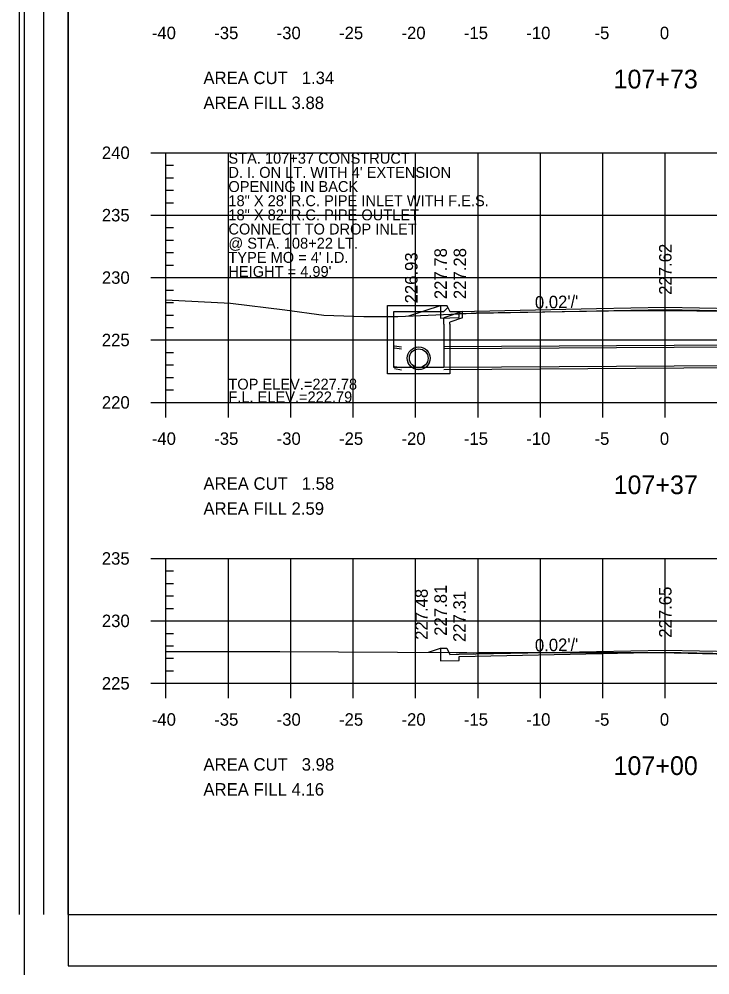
# Model space of a CAD drawing. Extents: x 1367903 to 1373764, y 376865 to 382130.
# Drawn here: x 1371640.9 to 1371751.5, y 377279.1 to 377432.3 of the extents above; entities that cross this region are included whole.
import ezdxf

# ---------------------------------------------------------------- set-up
doc = ezdxf.new("R2010")
doc.units = 0
for name, color, linetype in [('R_Axis', 7, 'Continuous'), ('R_Axis Annot', 7, 'Continuous'), ('R_Border', 7, 'Continuous'), ('R_Border PE', 7, 'Continuous'), ('R_Draft', 7, 'Continuous'), ('R_Exist Surface', 7, 'Continuous'), ('R_Fin Surface', 7, 'Continuous'), ('R_Fin Surface Annot', 7, 'Continuous'), ('R_Grid', 7, 'Continuous'), ('R_Water', 7, 'Continuous'), ('R_Water Annot', 7, 'Continuous')]:
    doc.layers.add(name, color=color, linetype=linetype)

msp = doc.modelspace()

# ---------------------------------------------------------------- linework, layer by layer
for p, q in [((1371699.89, 377386.39), (1371709.39, 377386.39)), ((1371699.89, 377383.39), (1371699.89, 377386.39)), ((1371709.56, 377386.06), (1371709.39, 377386.39)), ((1371700.89, 377383.39), (1371700.89, 377385.39)), ((1371700.89, 377385.39), (1371708.89, 377385.39)), ((1371709.56, 377386.06), (1371708.89, 377385.39)), ((1371711.89, 377385.43), (1371708.89, 377384.39)), ((1371708.89, 377383.39), (1371708.89, 377384.39)), ((1371711.89, 377384.37), (1371709.89, 377383.68)), ((1371709.89, 377383.39), (1371709.89, 377383.68))]:
    msp.add_line(p, q)
for points in [[(1371708.39, 377386.39), (1371708.39, 377385.72), (1371708.39, 377385.72), (1371708.39, 377384.36), (1371711.39, 377384.42), (1371711.39, 377385.09), (1371744.39, 377385.75), (1371777.39, 377385.09), (1371777.39, 377384.42), (1371780.39, 377384.36), (1371780.39, 377385.8), (1371794.39, 377386.08), (1371794.39, 377386.67)], [(1371711.89, 377384.37), (1371711.89, 377385.43)], [(1371708.39, 377331.45), (1371708.39, 377330.78), (1371708.39, 377330.78), (1371708.39, 377329.42), (1371711.39, 377329.48), (1371711.39, 377330.14), (1371744.39, 377330.8), (1371777.39, 377330.14), (1371777.39, 377329.48), (1371780.39, 377329.42), (1371780.39, 377330.86), (1371794.39, 377331.14), (1371794.39, 377331.73)]]:
    msp.add_lwpolyline(points)
at = {"layer": 'R_Axis'}
for p, q in [((1371661.99, 377410.84), (1371666.79, 377410.84)), ((1371664.39, 377370.84), (1371664.39, 377410.84)), ((1371664.39, 377408.84), (1371665.59, 377408.84)), ((1371664.39, 377406.84), (1371665.59, 377406.84)), ((1371664.39, 377404.84), (1371665.59, 377404.84)), ((1371664.39, 377402.84), (1371665.59, 377402.84)), ((1371661.99, 377400.84), (1371666.79, 377400.84)), ((1371664.39, 377398.84), (1371665.59, 377398.84)), ((1371664.39, 377396.84), (1371665.59, 377396.84)), ((1371664.39, 377394.84), (1371665.59, 377394.84)), ((1371664.39, 377392.84), (1371665.59, 377392.84)), ((1371661.99, 377390.84), (1371666.79, 377390.84)), ((1371664.39, 377388.84), (1371665.59, 377388.84)), ((1371664.39, 377386.84), (1371665.59, 377386.84)), ((1371664.39, 377384.84), (1371665.59, 377384.84)), ((1371664.39, 377382.84), (1371665.59, 377382.84)), ((1371661.99, 377380.84), (1371666.79, 377380.84)), ((1371664.39, 377378.84), (1371665.59, 377378.84)), ((1371664.39, 377376.84), (1371665.59, 377376.84)), ((1371664.39, 377374.84), (1371665.59, 377374.84)), ((1371664.39, 377368.44), (1371664.39, 377373.24)), ((1371664.39, 377372.84), (1371665.59, 377372.84)), ((1371674.39, 377368.44), (1371674.39, 377373.24)), ((1371684.39, 377368.44), (1371684.39, 377373.24)), ((1371694.39, 377368.44), (1371694.39, 377373.24)), ((1371704.39, 377368.44), (1371704.39, 377373.24)), ((1371714.39, 377368.44), (1371714.39, 377373.24)), ((1371724.39, 377368.44), (1371724.39, 377373.24)), ((1371734.39, 377368.44), (1371734.39, 377373.24)), ((1371744.39, 377368.44), (1371744.39, 377373.24)), ((1371661.99, 377370.84), (1371666.79, 377370.84)), ((1371664.39, 377370.84), (1371824.39, 377370.84)), ((1371661.99, 377345.84), (1371666.79, 377345.84)), ((1371664.39, 377325.84), (1371664.39, 377345.84)), ((1371664.39, 377343.84), (1371665.59, 377343.84)), ((1371664.39, 377341.84), (1371665.59, 377341.84)), ((1371664.39, 377339.84), (1371665.59, 377339.84)), ((1371664.39, 377337.84), (1371665.59, 377337.84)), ((1371661.99, 377335.84), (1371666.79, 377335.84)), ((1371664.39, 377333.84), (1371665.59, 377333.84)), ((1371664.39, 377331.84), (1371665.59, 377331.84)), ((1371664.39, 377329.84), (1371665.59, 377329.84)), ((1371664.39, 377323.44), (1371664.39, 377328.24)), ((1371674.39, 377323.44), (1371674.39, 377328.24)), ((1371684.39, 377323.44), (1371684.39, 377328.24)), ((1371694.39, 377323.44), (1371694.39, 377328.24)), ((1371704.39, 377323.44), (1371704.39, 377328.24)), ((1371714.39, 377323.44), (1371714.39, 377328.24)), ((1371724.39, 377323.44), (1371724.39, 377328.24)), ((1371734.39, 377323.44), (1371734.39, 377328.24)), ((1371744.39, 377323.44), (1371744.39, 377328.24)), ((1371664.39, 377327.84), (1371665.59, 377327.84)), ((1371661.99, 377325.84), (1371666.79, 377325.84)), ((1371664.39, 377325.84), (1371824.39, 377325.84))]:
    msp.add_line(p, q, dxfattribs=at)
at = {"layer": 'R_Border'}
for p, q in [((1371641.67, 377620.35), (1371641.67, 377279.12)), ((1371648.7, 377611.47), (1371648.7, 377280.59)), ((1371648.7, 377280.59), (1371853.02, 377280.59))]:
    msp.add_line(p, q, dxfattribs=at)
at = {"layer": 'R_Border PE'}
for p, q in [((1371640.86, 377610.76), (1371640.86, 377288.8)), ((1371644.78, 377610.76), (1371644.78, 377288.8)), ((1371648.7, 377288.8), (1371648.7, 377603.25)), ((1371648.7, 377288.8), (1371853.02, 377288.8))]:
    msp.add_line(p, q, dxfattribs=at)
at = {"layer": 'R_Exist Surface'}
for points in [[(1371664.39, 377387.29), (1371674.74, 377386.73), (1371683.43, 377385.69), (1371689.66, 377384.8), (1371696.09, 377384.61), (1371699.77, 377384.61), (1371701.55, 377384.62), (1371712.51, 377385.11), (1371714.07, 377385.21), (1371735.27, 377385.51), (1371744.18, 377385.56), (1371770.56, 377385.28)], [(1371664.39, 377330.91), (1371665.54, 377330.91), (1371674.77, 377330.92), (1371681.18, 377330.93), (1371682.62, 377330.94), (1371710.88, 377330.77), (1371712.59, 377330.75), (1371713.63, 377330.72), (1371714.43, 377330.75), (1371735.16, 377330.79), (1371743.54, 377330.77), (1371752.6, 377330.57), (1371775.6, 377330.13), (1371790.12, 377330.27), (1371796.83, 377330.23), (1371797.49, 377330.25), (1371798.79, 377330.28), (1371824.39, 377330.46)]]:
    msp.add_lwpolyline(points, dxfattribs=at)
at = {"layer": 'R_Fin Surface'}
for points in [[(1371703.31, 377384.7), (1371708.39, 377386.39), (1371709.39, 377386.39), (1371709.89, 377385.39), (1371711.39, 377385.42), (1371733.39, 377385.86), (1371744.39, 377386.08), (1371755.39, 377385.86), (1371777.39, 377385.42), (1371778.89, 377385.39), (1371779.39, 377386.39), (1371780.39, 377386.39), (1371784.39, 377386.47), (1371794.39, 377386.67), (1371796.2, 377386.07)], [(1371706.45, 377330.8), (1371708.39, 377331.45), (1371709.39, 377331.45), (1371709.89, 377330.45), (1371711.39, 377330.48), (1371733.39, 377330.92), (1371744.39, 377331.14), (1371755.39, 377330.92), (1371777.39, 377330.48), (1371778.89, 377330.45), (1371779.39, 377331.45), (1371780.39, 377331.45), (1371784.39, 377331.53), (1371794.39, 377331.73), (1371798.73, 377330.28)]]:
    msp.add_lwpolyline(points, dxfattribs=at)
at = {"layer": 'R_Grid'}
for p, q in [((1371664.39, 377410.84), (1371824.39, 377410.84)), ((1371664.39, 377370.84), (1371664.39, 377410.84)), ((1371674.39, 377370.84), (1371674.39, 377410.84)), ((1371684.39, 377370.84), (1371684.39, 377410.84)), ((1371694.39, 377370.84), (1371694.39, 377410.84)), ((1371704.39, 377370.84), (1371704.39, 377410.84)), ((1371714.39, 377370.84), (1371714.39, 377410.84)), ((1371724.39, 377370.84), (1371724.39, 377410.84)), ((1371734.39, 377370.84), (1371734.39, 377410.84)), ((1371744.39, 377370.84), (1371744.39, 377410.84)), ((1371664.39, 377400.84), (1371824.39, 377400.84)), ((1371664.39, 377390.84), (1371824.39, 377390.84)), ((1371664.39, 377380.84), (1371824.39, 377380.84)), ((1371664.39, 377370.84), (1371824.39, 377370.84)), ((1371664.39, 377345.84), (1371824.39, 377345.84)), ((1371664.39, 377325.84), (1371664.39, 377345.84)), ((1371674.39, 377325.84), (1371674.39, 377345.84)), ((1371684.39, 377325.84), (1371684.39, 377345.84)), ((1371694.39, 377325.84), (1371694.39, 377345.84)), ((1371704.39, 377325.84), (1371704.39, 377345.84)), ((1371714.39, 377325.84), (1371714.39, 377345.84)), ((1371724.39, 377325.84), (1371724.39, 377345.84)), ((1371734.39, 377325.84), (1371734.39, 377345.84)), ((1371744.39, 377325.84), (1371744.39, 377345.84)), ((1371664.39, 377335.84), (1371824.39, 377335.84)), ((1371664.39, 377325.84), (1371824.39, 377325.84))]:
    msp.add_line(p, q, dxfattribs=at)
at = {"layer": 'R_Water'}
for p, q in [((1371779.89, 377380.17), (1371708.89, 377379.75)), ((1371701.03, 377379.92), (1371702.12, 377379.75)), ((1371701.03, 377379.59), (1371702.12, 377379.42)), ((1371779.89, 377379.84), (1371708.89, 377379.42)), ((1371701.03, 377376.59), (1371702.12, 377376.42)), ((1371701.03, 377376.25), (1371702.12, 377376.08)), ((1371779.89, 377376.84), (1371708.89, 377376.42)), ((1371779.89, 377376.51), (1371708.89, 377376.08))]:
    msp.add_line(p, q, dxfattribs=at)
for points in [[(1371709.89, 377383.39), (1371709.89, 377375.41), (1371704.89, 377375.41), (1371699.89, 377375.41), (1371699.89, 377383.39)], [(1371708.89, 377383.39), (1371708.89, 377376.41), (1371704.89, 377376.41), (1371700.89, 377376.41), (1371700.89, 377383.39)]]:
    msp.add_lwpolyline(points, dxfattribs=at)
for centre, radius in [((1371704.89, 377377.91), 1.83), ((1371704.89, 377377.92), 1.83), ((1371704.89, 377377.92), 1.5), ((1371704.89, 377377.91), 1.5)]:
    msp.add_circle(centre, radius, dxfattribs=at)

# ---------------------------------------------------------------- texts
at = {"layer": 'R_Axis Annot'}
for s, height, p in [('-40', 2, (1371662.12, 377429.04)), ('-35', 2, (1371672.12, 377429.04)), ('-30', 2, (1371682.12, 377429.04)), ('-25', 2, (1371692.12, 377429.04)), ('-20', 2, (1371702.12, 377429.04)), ('-15', 2, (1371712.12, 377429.04)), ('-10', 2, (1371722.12, 377429.04)), ('-5', 2, (1371733.05, 377429.04)), ('0', 2, (1371743.52, 377429.04)), ('AREA CUT   1.34', 2, (1371670.39, 377421.84)), ('107+73', 3, (1371736.1, 377421.14)), ('AREA FILL 3.88', 2, (1371670.39, 377417.84)), ('240', 2, (1371654.12, 377409.84)), ('235', 2, (1371654.11, 377399.84)), ('230', 2, (1371654.12, 377389.84)), ('225', 2, (1371654.11, 377379.84)), ('220', 2, (1371654.12, 377369.84)), ('-40', 2, (1371662.12, 377364.04)), ('-35', 2, (1371672.12, 377364.04)), ('-30', 2, (1371682.12, 377364.04)), ('-25', 2, (1371692.12, 377364.04)), ('-20', 2, (1371702.12, 377364.04)), ('-15', 2, (1371712.12, 377364.04)), ('-10', 2, (1371722.12, 377364.04)), ('-5', 2, (1371733.05, 377364.04)), ('0', 2, (1371743.52, 377364.04)), ('AREA CUT   1.58', 2, (1371670.39, 377356.84)), ('107+37', 3, (1371736.11, 377356.14)), ('AREA FILL 2.59', 2, (1371670.39, 377352.84)), ('235', 2, (1371654.11, 377344.84)), ('230', 2, (1371654.12, 377334.84)), ('225', 2, (1371654.11, 377324.84)), ('-40', 2, (1371662.12, 377319.04)), ('-35', 2, (1371672.12, 377319.04)), ('-30', 2, (1371682.12, 377319.04)), ('-25', 2, (1371692.12, 377319.04)), ('-20', 2, (1371702.12, 377319.04)), ('-15', 2, (1371712.12, 377319.04)), ('-10', 2, (1371722.12, 377319.04)), ('-5', 2, (1371733.05, 377319.04)), ('0', 2, (1371743.52, 377319.04)), ('AREA CUT   3.98', 2, (1371670.39, 377311.84)), ('107+00', 3, (1371736.1, 377311.14)), ('AREA FILL 4.16', 2, (1371670.39, 377307.84))]:
    msp.add_text(s, height=height, dxfattribs=at).set_placement(p)
at = {"layer": 'R_Draft'}
for s, p in [('STA. 107+37 CONSTRUCT', (1371674.39, 377409.09)), ("D. I. ON LT. WITH 4' EXTENSION", (1371674.39, 377406.82)), ('OPENING IN BACK', (1371674.39, 377404.55)), ('18" X 28\' R.C. PIPE INLET WITH F.E.S.', (1371674.39, 377402.28)), ('18" X 82\' R.C. PIPE OUTLET', (1371674.39, 377400.01)), ('CONNECT TO DROP INLET', (1371674.39, 377397.74)), ('@ STA. 108+22 LT.', (1371674.39, 377395.47)), ("TYPE MO = 4' I.D.", (1371674.39, 377393.2)), ("HEIGHT = 4.99'", (1371674.39, 377390.94))]:
    msp.add_text(s, height=1.75, dxfattribs=at).set_placement(p)
at = {"layer": 'R_Fin Surface Annot'}
for s, rotation, p in [('227.62', 90, (1371745.39, 377388.08)), ('226.93', 90, (1371704.69, 377386.7)), ('227.78', 90, (1371709.39, 377387.38)), ('227.28', 90, (1371712.48, 377387.39)), ("0.02'/'", 1.1457, (1371723.52, 377385.86)), ('227.48', 90, (1371706.33, 377332.8)), ('227.81', 90, (1371709.39, 377333.45)), ('227.31', 90, (1371712.42, 377332.45)), ('227.65', 90, (1371745.39, 377333.14)), ("0.02'/'", 1.1458, (1371723.52, 377330.92))]:
    msp.add_text(s, height=2, rotation=rotation, dxfattribs=at).set_placement(p)
at = {"layer": 'R_Water Annot'}
for s, p in [('TOP ELEV.=227.78', (1371674.39, 377372.89)), ('F.L. ELEV.=222.79', (1371674.39, 377370.84))]:
    msp.add_text(s, height=1.75, dxfattribs=at).set_placement(p)

doc.saveas('drawing.dxf')
